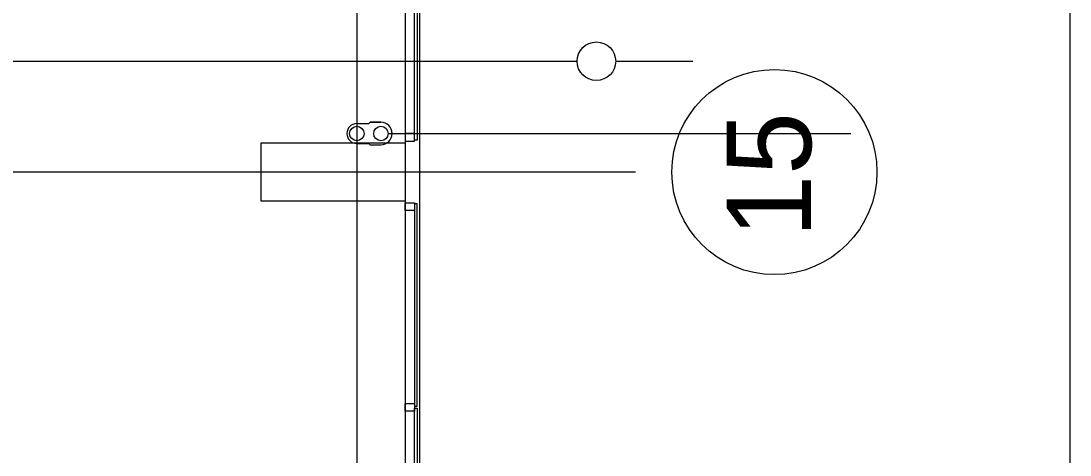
# Model space of a CAD drawing. Extents: x -264222 to -263592, y -1242345 to -1242048.
# Drawn here: x -263799.03 to -263788.14, y -1242177.82 to -1242173.31 of the extents above; entities that cross this region are included whole.
import ezdxf

# ---------------------------------------------------------------- set-up
doc = ezdxf.new("R2010")
doc.units = 0
doc.layers.add('HESCON_OSI_STAVBY_KFA', color=7, linetype='Continuous')
doc.layers.add('KFA_2D_SITUACIA_DSP', color=7, linetype='Continuous')

msp = doc.modelspace()

# ---------------------------------------------------------------- linework, layer by layer
at = {"layer": 'HESCON_OSI_STAVBY_KFA'}
for p, q in [((-263795.543, -1242083.237), (-263795.543, -1242246.707)), ((-263792.653, -1242174.882), (-263909.343, -1242174.882)), ((-263792.653, -1242174.882), (-263792.653, -1242174.882))]:
    msp.add_line(p, q, dxfattribs=at)
msp.add_circle((-263791.21, -1242174.882), 1.064, dxfattribs=at)
at = {"layer": 'KFA_2D_SITUACIA_DSP'}
for p, q in [((-263788.143, -1242250.14), (-263788.143, -1242082.64)), ((-263795.043, -1242101.769), (-263795.043, -1242226.995)), ((-263794.943, -1242174.552), (-263794.943, -1242172.452)), ((-263794.918, -1242172.452), (-263794.918, -1242174.552)), ((-263800.593, -1242173.732), (-263793.257, -1242173.732)), ((-263792.857, -1242173.732), (-263792.057, -1242173.732)), ((-263795.543, -1242174.379), (-263795.418, -1242174.379)), ((-263795.418, -1242174.379), (-263795.404, -1242174.365)), ((-263795.293, -1242174.365), (-263795.404, -1242174.365)), ((-263795.404, -1242174.365), (-263795.293, -1242174.365)), ((-263795.218, -1242174.482), (-263790.416, -1242174.482)), ((-263794.943, -1242174.482), (-263795.043, -1242174.482)), ((-263795.043, -1242174.482), (-263795.043, -1242174.562)), ((-263794.943, -1242174.522), (-263794.943, -1242174.482)), ((-263794.943, -1242174.562), (-263794.943, -1242174.522)), ((-263795.038, -1242174.582), (-263796.538, -1242174.582)), ((-263796.538, -1242174.582), (-263796.538, -1242175.182)), ((-263795.543, -1242174.585), (-263795.418, -1242174.585)), ((-263795.418, -1242174.585), (-263795.404, -1242174.599)), ((-263795.404, -1242174.599), (-263795.293, -1242174.599)), ((-263795.043, -1242174.562), (-263794.943, -1242174.562)), ((-263795.038, -1242175.182), (-263795.038, -1242174.582)), ((-263794.918, -1242174.552), (-263794.943, -1242174.552)), ((-263796.538, -1242175.182), (-263795.038, -1242175.182)), ((-263795.043, -1242175.282), (-263795.043, -1242175.202)), ((-263795.043, -1242175.202), (-263794.943, -1242175.202)), ((-263794.943, -1242175.282), (-263795.043, -1242175.282)), ((-263794.943, -1242175.202), (-263794.943, -1242175.242)), ((-263794.918, -1242175.212), (-263794.943, -1242175.212)), ((-263794.943, -1242175.212), (-263794.943, -1242177.312)), ((-263794.943, -1242175.242), (-263794.943, -1242175.282)), ((-263794.918, -1242177.312), (-263794.918, -1242175.212)), ((-263795.043, -1242177.362), (-263795.043, -1242177.282)), ((-263795.043, -1242177.282), (-263794.943, -1242177.282)), ((-263794.943, -1242177.362), (-263795.043, -1242177.362)), ((-263794.943, -1242177.282), (-263794.943, -1242177.322)), ((-263794.943, -1242177.312), (-263794.918, -1242177.312)), ((-263794.943, -1242177.322), (-263794.943, -1242177.362)), ((-263794.943, -1242179.432), (-263794.943, -1242177.332)), ((-263794.943, -1242177.332), (-263794.918, -1242177.332)), ((-263794.918, -1242177.332), (-263794.918, -1242179.432))]:
    msp.add_line(p, q, dxfattribs=at)
msp.add_lwpolyline([(-263794.893, -1242227.382), (-263808.968, -1242241.457), (-263894.968, -1242241.457), (-263909.043, -1242227.382), (-263909.043, -1242196.333), (-263914.143, -1242196.333), (-263914.143, -1242132.433), (-263909.043, -1242132.433), (-263909.043, -1242101.382), (-263894.968, -1242087.307), (-263808.968, -1242087.307), (-263794.893, -1242101.382), (-263794.893, -1242227.382)], dxfattribs=at)
for centre, radius in [((-263793.057, -1242173.732), 0.2), ((-263795.543, -1242174.482), 0.075), ((-263795.293, -1242174.482), 0.075)]:
    msp.add_circle(centre, radius, dxfattribs=at)
for centre, radius, start, end in [((-263795.543, -1242174.482), 0.103, 90, 270), ((-263795.293, -1242174.482), 0.117, 270, 90)]:
    msp.add_arc(centre, radius, start, end, dxfattribs=at)

# ---------------------------------------------------------------- texts
at = {"layer": 'HESCON_OSI_STAVBY_KFA'}
msp.add_text('15', height=0.875, rotation=90, dxfattribs=at).set_placement((-263790.829, -1242175.562))

doc.saveas('drawing.dxf')
